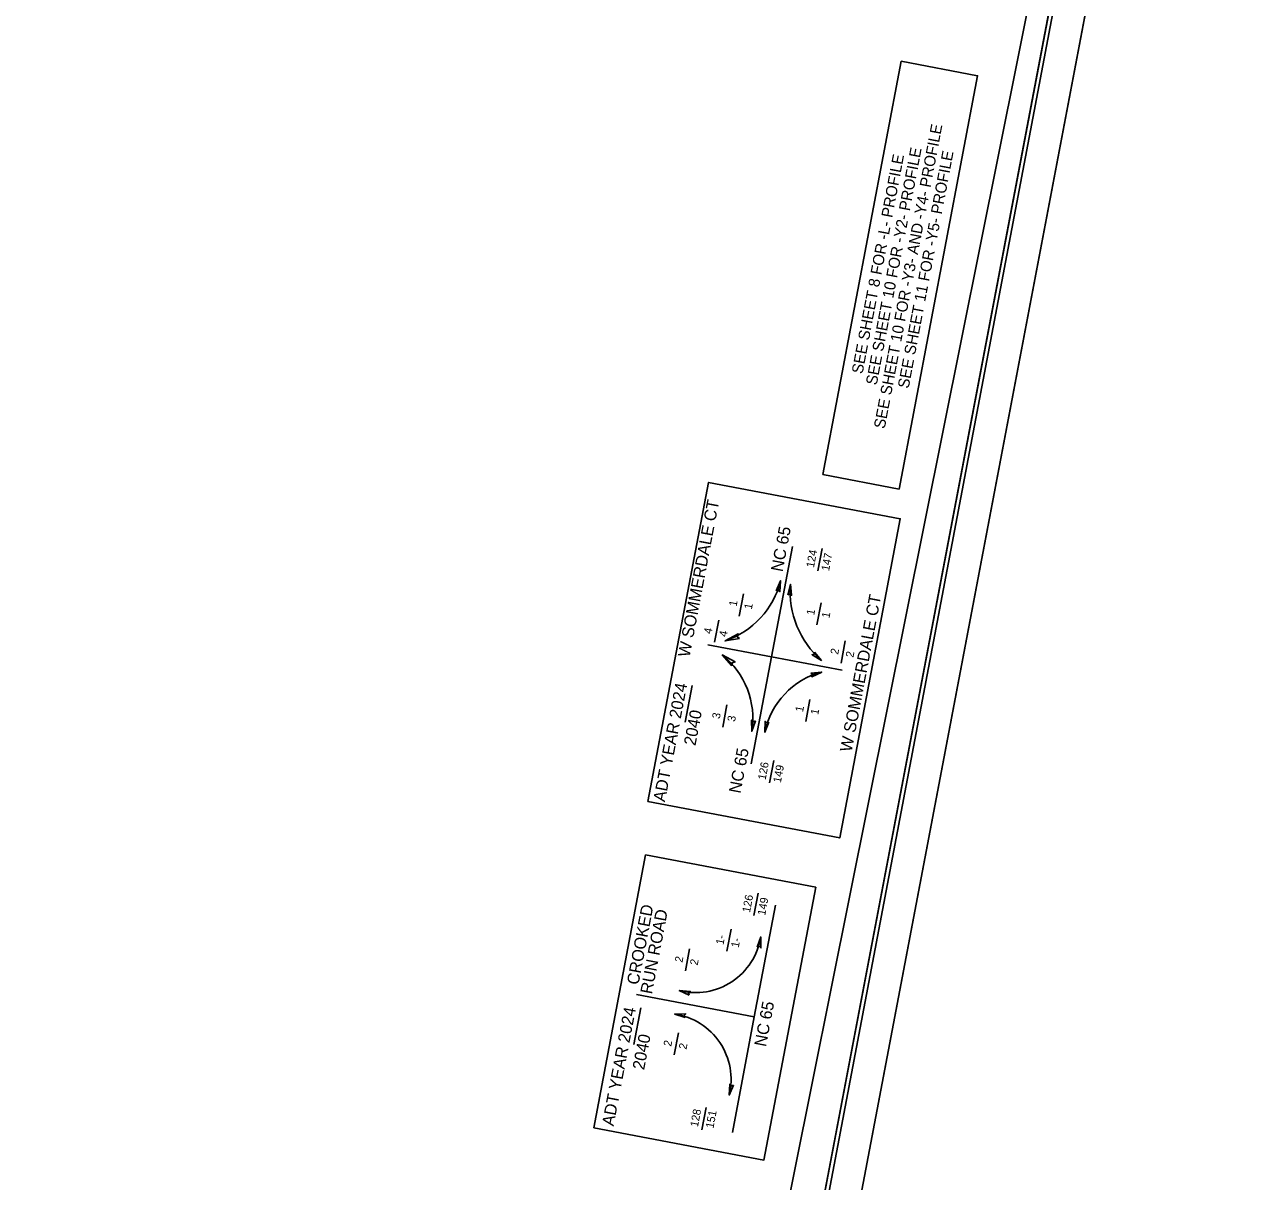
# Model space of a CAD drawing. Extents: x 1615685 to 1617075, y 899072 to 901363.
# Drawn here: x 1616307 to 1617075, y 899679 to 900402 of the extents above; entities that cross this region are included whole.
import ezdxf

# ---------------------------------------------------------------- set-up
doc = ezdxf.new("R2010")
doc.units = 0
for name, color, linetype in [('Exist Plan Preparation Drainage Flow Arrows', 7, 'Continuous'), ('Exist Plan Preparation Drainage Notes Label', 7, 'Continuous'), ('Exist Structure Minor Catch Basin', 7, 'Continuous'), ('Exist Structure Minor Pipes CMP 24 Inch Text', 7, 'Continuous'), ('Exist Structure Minor Pipes RCP 15 Inch', 7, 'Continuous'), ('Prop Drainage Structure Catch Basin Grate 840 03E CELL', 7, 'Continuous'), ('Prop Drainage Structure Drop Inlet Grate 840 16 CELL', 7, 'Continuous'), ('Prop Drainage Structure Plot Symbol 20 Scale', 7, 'Continuous'), ('Scratch_Level_0', 7, 'Continuous'), ('Scratch_Level_8', 7, 'Continuous')]:
    doc.layers.add(name, color=color, linetype=linetype)

msp = doc.modelspace()

# ---------------------------------------------------------------- linework, layer by layer
at = {"layer": 'Exist Plan Preparation Drainage Flow Arrows'}
msp.add_lwpolyline([(1616744, 899325.3), (1617054.75, 900962.05), (1616018.28, 901158.86), (1615707.51, 899522.1)], close=True, dxfattribs=at)
at = {"layer": 'Exist Plan Preparation Drainage Notes Label'}
msp.add_lwpolyline([(1616761.22, 899308.8), (1617075.25, 900962.75), (1615999.47, 901167.01), (1615685.44, 899513.06)], close=True, dxfattribs=at)
at = {"layer": 'Exist Structure Minor Catch Basin'}
for p, q in [((1616774.02, 900007.29), (1616787.12, 900076.28)), ((1616803.09, 900061.11), (1616805.72, 900074.95)), ((1616753.97, 900032.7), (1616756.6, 900046.55)), ((1616802.47, 900027.24), (1616805.09, 900041.08)), ((1616738.45, 900016.34), (1616741.08, 900030.19)), ((1616734.32, 900014.83), (1616774.02, 900007.29)), ((1616817.57, 900003.37), (1616820.2, 900017.21)), ((1616761.31, 899940.34), (1616774.02, 900007.29)), ((1616774.02, 900007.29), (1616818.25, 899998.89)), ((1616720.04, 899966.34), (1616724.41, 899989.35)), ((1616743.64, 899963.33), (1616746.27, 899977.18)), ((1616795.48, 899966.76), (1616798.11, 899980.6)), ((1616772.91, 899928.56), (1616775.54, 899942.4)), ((1616763.15, 899845.65), (1616765.78, 899859.49)), ((1616763.35, 899782.17), (1616776.62, 899852.09)), ((1616746.17, 899823.3), (1616748.8, 899837.14)), ((1616720.26, 899810.95), (1616722.89, 899824.79)), ((1616763.35, 899782.17), (1616689.73, 899796.15)), ((1616687.98, 899764.92), (1616692.35, 899787.92)), ((1616749.65, 899710), (1616763.35, 899782.17)), ((1616713.27, 899758.43), (1616715.89, 899772.27)), ((1616730.63, 899711.68), (1616733.25, 899725.52))]:
    msp.add_line(p, q, dxfattribs=at)
for points in [[(1616696.91, 899916.82), (1616734.79, 900116.31), (1616854.59, 900093.56), (1616816.71, 899894.07)], [(1616663.03, 899712.89), (1616695.4, 899883.41), (1616801.76, 899863.21), (1616769.39, 899692.69)]]:
    msp.add_lwpolyline(points, close=True, dxfattribs=at)
for centre, radius, start, end in [((1616728.17, 900067.7), 53.22, 288.58018, 346.0112), ((1616842.46, 900047.77), 56.67, 175.11177, 229.036), ((1616712, 899968.9), 50.43, 350.73454, 51.67155), ((1616818.17, 899950.2), 49.25, 104.98346, 168.36039), ((1616726.56, 899838.68), 41.3, 255.82647, 350.94262), ((1616707.51, 899743.13), 41.3, 346.31069, 81.42684)]:
    msp.add_arc(centre, radius, start, end, dxfattribs=at)
at = {"layer": 'Exist Structure Minor Pipes CMP 24 Inch Text'}
msp.add_line((1616761.22, 899308.8), (1617075.25, 900962.75), dxfattribs=at)
at = {"layer": 'Exist Structure Minor Pipes RCP 15 Inch'}
for points in [[(1616777.05, 900048.56), (1616779.81, 900054.83), (1616779.33, 900047.95), (1616778.38, 900049.08)], [(1616777.05, 900048.56), (1616779.81, 900054.83), (1616779.33, 900047.95), (1616778.38, 900049.08)], [(1616784.26, 900045.98), (1616786, 900052.6), (1616786.61, 900045.74), (1616785.49, 900046.7)], [(1616784.26, 900045.98), (1616786, 900052.6), (1616786.61, 900045.74), (1616785.49, 900046.7)], [(1616754.15, 900018.65), (1616745.13, 900017.25), (1616753.2, 900021.65), (1616752.61, 900019.77)], [(1616749.38, 900001.67), (1616743.28, 900008.46), (1616751.37, 900004.11), (1616749.47, 900003.56)], [(1616800.98, 900010.28), (1616805.31, 900004.98), (1616799.4, 900008.52), (1616800.84, 900008.86)], [(1616800.98, 900010.28), (1616805.31, 900004.98), (1616799.4, 900008.52), (1616800.84, 900008.86)], [(1616798.62, 899997.14), (1616805.44, 899997.77), (1616799.19, 899994.85), (1616799.72, 899996.24)], [(1616798.62, 899997.14), (1616805.44, 899997.77), (1616799.19, 899994.85), (1616799.72, 899996.24)], [(1616764.01, 899967.26), (1616761.77, 899960.78), (1616761.68, 899967.68), (1616762.73, 899966.63)], [(1616772.44, 899966.51), (1616769.94, 899960.13), (1616770.13, 899967.02), (1616771.14, 899965.93)], [(1616765.14, 899825.7), (1616767.35, 899832.18), (1616767.47, 899825.29), (1616766.42, 899826.33)], [(1616765.14, 899825.7), (1616767.35, 899832.18), (1616767.47, 899825.29), (1616766.42, 899826.33)], [(1616722.71, 899795.86), (1616716.45, 899798.64), (1616723.32, 899798.14), (1616722.19, 899797.19)], [(1616722.71, 899795.86), (1616716.45, 899798.64), (1616723.32, 899798.14), (1616722.19, 899797.19)], [(1616720.16, 899781.81), (1616713.66, 899783.97), (1616720.55, 899784.14), (1616719.52, 899783.08)], [(1616720.16, 899781.81), (1616713.66, 899783.97), (1616720.55, 899784.14), (1616719.52, 899783.08)], [(1616750.36, 899739.63), (1616747.64, 899733.35), (1616748.08, 899740.23), (1616749.04, 899739.11)], [(1616750.36, 899739.63), (1616747.64, 899733.35), (1616748.08, 899740.23), (1616749.04, 899739.11)]]:
    msp.add_lwpolyline(points, close=True, dxfattribs=at)
at = {"layer": 'Prop Drainage Structure Catch Basin Grate 840 03E CELL'}
msp.add_lwpolyline([(1616779.49, 899525.69), (1617040.64, 900901.13), (1616216.84, 901057.54), (1616181.54, 900871.6), (1615973.76, 900911.05), (1615747.91, 899721.55)], close=True, dxfattribs=at)
at = {"layer": 'Prop Drainage Structure Drop Inlet Grate 840 16 CELL'}
msp.add_lwpolyline([(1615738.61, 899672.4), (1616770.16, 899476.57), (1617049.96, 900950.24), (1616226.17, 901106.65), (1616181.54, 900871.6), (1615973.76, 900911.05)], close=True, dxfattribs=at)
at = {"layer": 'Prop Drainage Structure Plot Symbol 20 Scale'}
msp.add_lwpolyline([(1616187.49, 901058.27), (1617032.97, 900874.07), (1617012.18, 900781.12), (1616950.6, 900773.34), (1616752.73, 900760.58), (1616722.43, 900593.62), (1616951.14, 900496.73), (1616753.23, 899510.43), (1615915.8, 899646.19), (1615751.76, 899738.03), (1615999.36, 900929.08), (1616157.93, 900902)], close=True, dxfattribs=at)
at = {"layer": 'Scratch_Level_0'}
msp.add_lwpolyline([(1616806.16, 900121.19), (1616855.21, 900379.52), (1616902.88, 900370.47), (1616853.84, 900112.14)], close=True, dxfattribs=at)
at = {"layer": 'Scratch_Level_8'}
for points in [[(1616018.4, 901146.14), (1615738.59, 899672.43), (1616770.16, 899476.57), (1617049.96, 900950.25)], [(1616770.16, 899476.57), (1615738.61, 899672.4), (1615981.06, 900949.58), (1616128.49, 900921.6), (1616165.82, 901118.12), (1617049.96, 900950.25)]]:
    msp.add_lwpolyline(points, close=True, dxfattribs=at)

# ---------------------------------------------------------------- texts
at = {"layer": 'Exist Structure Minor Catch Basin'}
for s, height, p in [('W SOMMERDALE CT', 7.5, (1616722.86, 900006.67)), ('NC 65', 7.5, (1616780.99, 900060.03)), ('124', 5, (1616800.58, 900062.72)), ('147', 5, (1616810.05, 900060.67)), ('W SOMMERDALE CT', 7.5, (1616824.1, 899947.41)), ('1', 5, (1616752.25, 900038.45)), ('1', 5, (1616761.77, 900036.64)), ('1', 5, (1616800.74, 900032.98)), ('1', 5, (1616810.26, 900031.18)), ('4', 5, (1616736.57, 900021.25)), ('4', 5, (1616746.09, 900019.45)), ('2', 5, (1616815.71, 900008.41)), ('2', 5, (1616825.23, 900006.6)), ('ADT YEAR 2024', 7.5, (1616707.48, 899916.23)), ('   2040', 7.5, (1616724.99, 899943.13)), ('3', 5, (1616741.75, 899968.21)), ('3', 5, (1616751.27, 899966.4)), ('1', 5, (1616793.76, 899972.5)), ('1', 5, (1616803.27, 899970.7)), ('NC 65', 7.5, (1616754.7, 899921.54)), ('126', 5, (1616770.38, 899930.05)), ('149', 5, (1616779.9, 899928.26)), ('126', 5, (1616760.62, 899847.14)), ('149', 5, (1616770.14, 899845.36)), ('CROOKED', 7.5, (1616690.93, 899801.88)), ('RUN ROAD', 7.5, (1616699.37, 899796.1)), ('1-', 5, (1616744.07, 899827.05)), ('1-', 5, (1616753.59, 899825.25)), ('2', 5, (1616718.4, 899815.98)), ('2', 5, (1616727.92, 899814.18)), ('NC 65', 7.5, (1616770.6, 899763.21)), ('ADT YEAR 2024', 7.5, (1616675.41, 899713.61)), ('   2040', 7.5, (1616692.92, 899740.51)), ('2', 5, (1616711.41, 899763.47)), ('2', 5, (1616720.93, 899761.66)), ('128', 5, (1616728.09, 899713.16)), ('151', 5, (1616737.79, 899712.32))]:
    msp.add_text(s, height=height, rotation=79.24937, dxfattribs=at).set_placement(p)
at = {"layer": 'Scratch_Level_0'}
for s, p in [('SEE SHEET 10 FOR -Y3- AND -Y4- PROFILE', (1616844.82, 900149.46)), ('SEE SHEET 10 FOR -Y2- PROFILE', (1616839.82, 900176.72)), ('SEE SHEET 11 FOR -Y5- PROFILE', (1616859.78, 900174.64)), ('SEE SHEET 8 FOR -L- PROFILE', (1616830.98, 900183.75))]:
    msp.add_text(s, height=7, rotation=79.24937, dxfattribs=at).set_placement(p)

doc.saveas('drawing.dxf')
